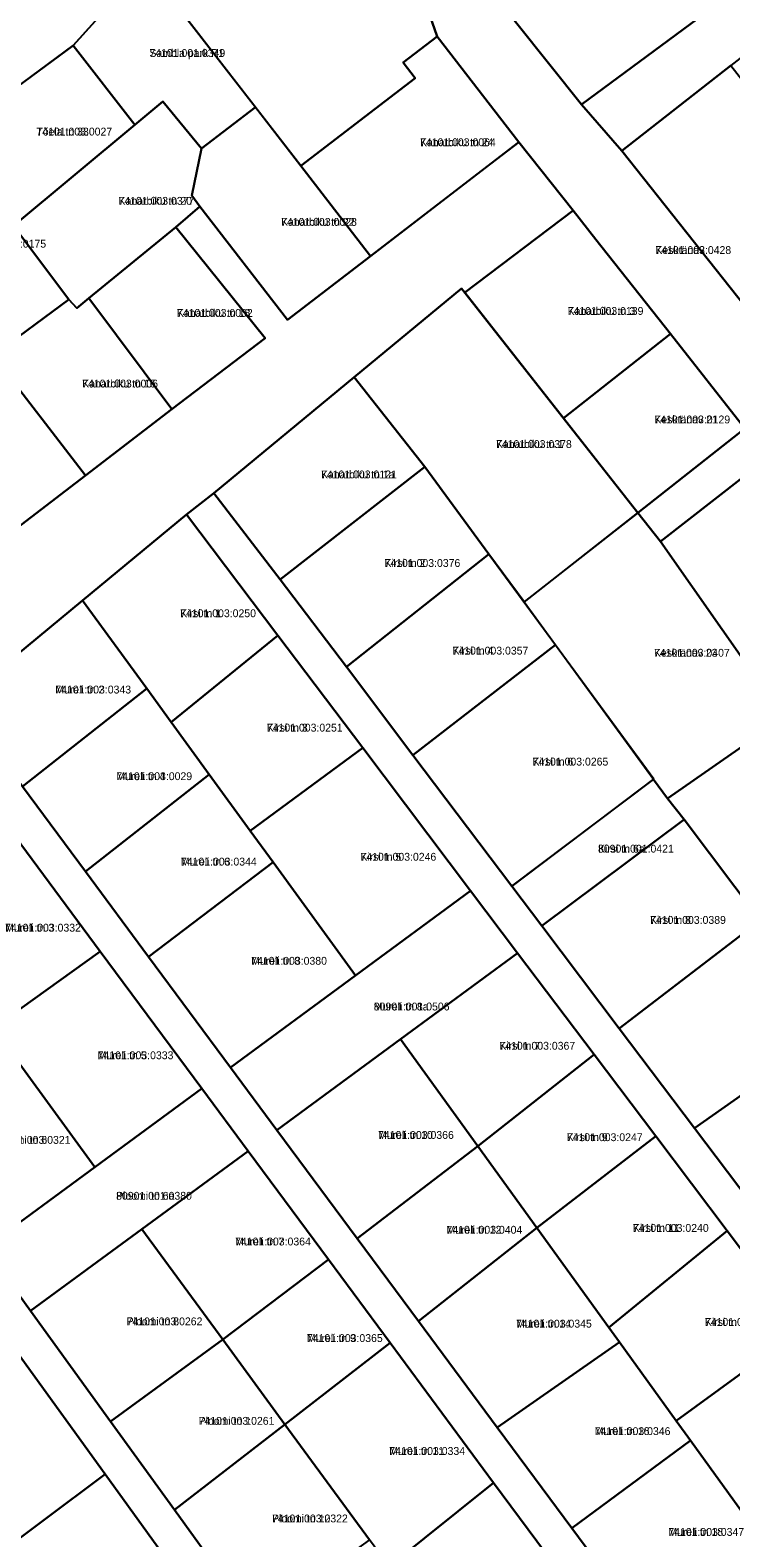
# Model space of a CAD drawing. Extents: x 524000 to 564260, y 6469338 to 6496391.
# Drawn here: x 538832.2 to 538966.3, y 6473209.4 to 6473497.9 of the extents above; entities that cross this region are included whole.
import ezdxf

# ---------------------------------------------------------------- set-up
doc = ezdxf.new("R2010")
doc.units = 0
for name, color, linetype in [('L_AADRESS', 7, 'Continuous'), ('PIIR', 7, 'Continuous'), ('TUNNUS', 7, 'Continuous')]:
    doc.layers.add(name, color=color, linetype=linetype)

msp = doc.modelspace()

# ---------------------------------------------------------------- linework, layer by layer
at = {"layer": 'PIIR'}
for points in [[(538790.44, 6473668.85), (538818.36, 6473633.78), (538821.51, 6473636.25), (538833.78, 6473620.41), (538846.45, 6473604.93), (538843.3, 6473602.49), (538860.15, 6473582.87), (538863.79, 6473577.89), (538881.97, 6473554.41), (538900.33, 6473530.7), (538918.99, 6473507.21), (538937.65, 6473483.72), (538945.42, 6473474.85), (538974.45, 6473438.22), (538987.99, 6473421.14), (539019.92, 6473380.27), (539033.35, 6473363.32), (539046.78, 6473346.15), (539060.21, 6473328.98), (539073.64, 6473311.81), (539082.11, 6473303.28), (539135.86, 6473234.01), (539149.77, 6473216.07), (539153.84, 6473218.89)], [(538973.59, 6473416.31), (538952.77, 6473400.07), (538948.47, 6473405.56), (538968.92, 6473421.73), (538954.69, 6473439.8), (538940.44, 6473457.89), (538936.11, 6473463.39), (538925.69, 6473476.49), (538910.07, 6473496.74), (538906.42, 6473507.17)], [(538795.36, 6473376.39), (538842.75, 6473412.69), (538859.26, 6473425.42), (538877.16, 6473439), (538860.04, 6473460.24), (538864.62, 6473464.21), (538881.44, 6473442.51), (538897.28, 6473454.71), (538925.69, 6473476.49), (538936.11, 6473463.39), (538915.37, 6473447.7), (538914.74, 6473448.5), (538894.18, 6473431.5), (538867.33, 6473409.3), (538862.09, 6473405.24), (538842.2, 6473388.81), (538818.72, 6473369.4)], [(538979.8, 6473249.3), (538965.56, 6473268.15), (538951.88, 6473286.28), (538940.1, 6473301.9), (538925.46, 6473321.29), (538916.46, 6473333.21), (538895.81, 6473360.57), (538879.58, 6473382.07), (538862.09, 6473405.24), (538867.33, 6473409.3), (538880.04, 6473392.82), (538892.7, 6473376.06), (538905.42, 6473359.21), (538924.36, 6473334.11), (538930.08, 6473326.52), (538944.9, 6473306.89), (538959.3, 6473287.82), (538971.92, 6473271.1)], [(538939.08, 6473195.34), (538920.87, 6473219.93), (538901.05, 6473246.69), (538889.24, 6473262.65), (538873.87, 6473283.41), (538865, 6473295.39), (538845.6, 6473321.61), (538829.29, 6473343.63), (538813.44, 6473365.04), (538818.72, 6473369.4), (538830.74, 6473353.18), (538842.79, 6473336.9), (538854.85, 6473320.6), (538870.51, 6473299.44), (538879.39, 6473287.45), (538894.78, 6473266.66), (538906.47, 6473250.87), (538921.54, 6473230.53), (538935.8, 6473211.27), (538950.43, 6473191.51)], [(538867.2, 6473192.97), (538846.51, 6473221.58), (538814.6, 6473265.73), (538803.57, 6473280.99), (538793.08, 6473295.5), (538782.67, 6473309.9), (538769.22, 6473328.51), (538774.43, 6473332.82), (538792.14, 6473308.32), (538806.26, 6473288.78), (538823.52, 6473264.91), (538832.26, 6473252.82), (538847.53, 6473231.69), (538859.8, 6473214.73), (538875.33, 6473193.24)]]:
    msp.add_lwpolyline(points, dxfattribs=at)
for points in [[(539082.21, 6473592.27), (539089.25, 6473583.53), (539062.91, 6473564.58), (539042.54, 6473549.92), (539021.31, 6473533.32), (538997.68, 6473514.83), (538986.76, 6473507.2), (538966.28, 6473491.18), (538945.42, 6473474.85), (538937.65, 6473483.72), (538977.91, 6473513.5), (538989.08, 6473522.31), (539013.41, 6473539.87), (539012.78, 6473540.65), (539033.15, 6473556.97), (539056.61, 6473573.98), (539079.77, 6473590.52)], [(538874.33, 6473545.46), (538883.08, 6473536.52), (538854.24, 6473510.36), (538840.44, 6473495.03), (538816.26, 6473477.19), (538801.85, 6473465.94), (538760.64, 6473420.14), (538745.93, 6473401.69), (538729.29, 6473380.83), (538718, 6473394.65), (538732.82, 6473416.15), (538732.08, 6473417.02), (538750.86, 6473441.68), (538751.83, 6473440.29), (538772.8, 6473468.56), (538782.98, 6473484.33), (538801.98, 6473508.7), (538815.58, 6473527.22), (538831.5, 6473506.61)], [(538918.99, 6473507.21), (538959.23, 6473536.98), (538977.91, 6473513.5), (538937.65, 6473483.72)], [(538906.42, 6473507.17), (538910.07, 6473496.74), (538903.58, 6473491.73), (538905.87, 6473488.76), (538883.99, 6473471.98), (538878.96, 6473478.47), (538854.24, 6473510.36), (538883.08, 6473536.52)], [(538852.18, 6473479.83), (538840.44, 6473495.03), (538854.24, 6473510.36), (538875.28, 6473483.21), (538864.96, 6473475.26), (538857.56, 6473484.31)], [(538883.99, 6473471.98), (538905.87, 6473488.76), (538903.58, 6473491.73), (538910.07, 6473496.74), (538925.69, 6473476.49), (538919.18, 6473471.5), (538897.28, 6473454.71)], [(538828.96, 6473460.5), (538816.26, 6473477.19), (538816.29, 6473477.21), (538840.44, 6473495.03), (538852.18, 6473479.83)], [(538980.5, 6473473), (538989.49, 6473460.78), (538994.43, 6473454.06), (538974.45, 6473438.22), (538945.42, 6473474.85), (538966.28, 6473491.18)], [(538860.04, 6473460.24), (538843.38, 6473446.66), (538841.08, 6473444.74), (538839.6, 6473446.42), (538828.96, 6473460.5), (538852.18, 6473479.83), (538857.56, 6473484.31), (538864.96, 6473475.26), (538863.11, 6473466.26), (538864.62, 6473464.21)], [(538881.44, 6473442.51), (538864.62, 6473464.21), (538863.11, 6473466.26), (538864.96, 6473475.26), (538875.28, 6473483.21), (538883.99, 6473471.98), (538897.28, 6473454.71)], [(538816.26, 6473477.19), (538828.96, 6473460.5), (538839.6, 6473446.42), (538825.02, 6473435.7), (538801.85, 6473465.94)], [(538801.85, 6473465.94), (538825.02, 6473435.7), (538842.75, 6473412.69), (538795.36, 6473376.39), (538780.2, 6473395.5), (538760.64, 6473420.14)], [(538915.37, 6473447.7), (538936.11, 6473463.39), (538940.44, 6473457.89), (538954.69, 6473439.8), (538934.26, 6473423.71), (538920.01, 6473441.8)], [(538860.04, 6473460.24), (538877.16, 6473439), (538859.26, 6473425.42), (538843.38, 6473446.66)], [(538907.72, 6473414.36), (538894.18, 6473431.5), (538914.74, 6473448.5), (538948.47, 6473405.56), (538926.7, 6473388.5), (538919.97, 6473397.66)], [(538839.6, 6473446.42), (538841.08, 6473444.74), (538843.38, 6473446.66), (538859.26, 6473425.42), (538842.75, 6473412.69), (538825.02, 6473435.7)], [(538934.26, 6473423.71), (538954.69, 6473439.8), (538968.92, 6473421.73), (538948.47, 6473405.56)], [(538907.72, 6473414.36), (538880.04, 6473392.82), (538867.33, 6473409.3), (538894.18, 6473431.5)], [(538973.59, 6473416.31), (538999.46, 6473383.2), (538976.38, 6473366.41), (538952.77, 6473400.07)], [(538880.04, 6473392.82), (538907.72, 6473414.36), (538919.97, 6473397.66), (538892.7, 6473376.06)], [(538879.58, 6473382.07), (538859.15, 6473365.53), (538854.5, 6473371.92), (538842.2, 6473388.81), (538862.09, 6473405.24)], [(538948.47, 6473405.56), (538952.77, 6473400.07), (538976.38, 6473366.41), (538954.12, 6473350.91), (538951.46, 6473354.55), (538932.72, 6473380.21), (538926.71, 6473388.44)], [(538932.73, 6473380.29), (538905.42, 6473359.21), (538892.7, 6473376.06), (538919.97, 6473397.66)], [(538854.5, 6473371.92), (538830.74, 6473353.18), (538818.72, 6473369.4), (538842.2, 6473388.81)], [(538895.81, 6473360.57), (538874.31, 6473344.7), (538866.44, 6473355.51), (538859.15, 6473365.53), (538879.58, 6473382.07)], [(538951.53, 6473354.67), (538924.36, 6473334.11), (538905.42, 6473359.21), (538932.73, 6473380.29)], [(538830.74, 6473353.18), (538854.5, 6473371.92), (538859.15, 6473365.53), (538866.44, 6473355.51), (538842.79, 6473336.9)], [(538976.38, 6473366.41), (539000.5, 6473336.39), (539002.72, 6473333.71), (538983.57, 6473319), (538980.21, 6473316.42), (538971.86, 6473327.53), (538957.3, 6473346.9), (538954.12, 6473350.91)], [(538874.31, 6473344.7), (538895.81, 6473360.57), (538916.46, 6473333.21), (538894.45, 6473317.04), (538878.67, 6473338.71)], [(538874.31, 6473344.7), (538878.67, 6473338.71), (538854.85, 6473320.6), (538842.79, 6473336.9), (538866.44, 6473355.51)], [(538957.3, 6473346.9), (538930.08, 6473326.52), (538924.36, 6473334.11), (538951.46, 6473354.55), (538954.12, 6473350.91)], [(538957.3, 6473346.9), (538971.86, 6473327.53), (538944.9, 6473306.89), (538930.08, 6473326.52)], [(538845.6, 6473321.61), (538825.18, 6473307.02), (538813.64, 6473322.92), (538809.17, 6473329.07), (538829.29, 6473343.63)], [(538854.85, 6473320.6), (538878.67, 6473338.71), (538894.45, 6473317.04), (538870.51, 6473299.44)], [(538903.07, 6473304.84), (538879.39, 6473287.45), (538870.51, 6473299.44), (538894.45, 6473317.04), (538916.46, 6473333.21), (538925.46, 6473321.29)], [(538944.9, 6473306.89), (538971.86, 6473327.53), (538980.21, 6473316.42), (538987.02, 6473307.32), (538959.3, 6473287.82)], [(538825.18, 6473307.02), (538845.6, 6473321.61), (538865, 6473295.39), (538844.54, 6473280.35), (538826.98, 6473304.53)], [(538903.07, 6473304.84), (538925.46, 6473321.29), (538940.1, 6473301.9), (538917.87, 6473284.34)], [(538959.3, 6473287.82), (538987.02, 6473307.32), (539000.34, 6473289.53), (538971.92, 6473271.1)], [(538806.26, 6473288.78), (538826.98, 6473304.53), (538844.54, 6473280.35), (538823.52, 6473264.91)], [(538879.39, 6473287.45), (538903.07, 6473304.84), (538917.87, 6473284.34), (538894.78, 6473266.66)], [(538951.88, 6473286.28), (538929.13, 6473268.75), (538917.87, 6473284.34), (538940.1, 6473301.9)], [(538853.54, 6473268.46), (538832.26, 6473252.82), (538823.52, 6473264.91), (538844.54, 6473280.35), (538865, 6473295.39), (538873.87, 6473283.41)], [(538929.13, 6473268.75), (538951.88, 6473286.28), (538965.56, 6473268.15), (538942.92, 6473249.65)], [(538853.54, 6473268.46), (538873.87, 6473283.41), (538889.24, 6473262.65), (538869.03, 6473247.35)], [(538917.87, 6473284.34), (538929.13, 6473268.75), (538906.47, 6473250.87), (538894.78, 6473266.66)], [(538832.26, 6473252.82), (538853.54, 6473268.46), (538869.03, 6473247.35), (538847.53, 6473231.69)], [(538906.47, 6473250.87), (538929.13, 6473268.75), (538942.92, 6473249.65), (538944.93, 6473246.86), (538921.54, 6473230.53)], [(538822.63, 6473203.75), (538794.97, 6473183.11), (538762.53, 6473227.53), (538791.04, 6473248.2), (538814.6, 6473265.73), (538846.51, 6473221.58)], [(538979.8, 6473249.3), (538955.82, 6473231.78), (538944.93, 6473246.86), (538942.92, 6473249.65), (538965.56, 6473268.15)], [(538869.03, 6473247.35), (538889.24, 6473262.65), (538901.05, 6473246.69), (538880.94, 6473231.12)], [(538958.51, 6473228.05), (538955.82, 6473231.78), (538979.8, 6473249.3), (538992.9, 6473231.95), (538969.45, 6473212.9)], [(538880.94, 6473231.12), (538859.8, 6473214.73), (538847.53, 6473231.69), (538869.03, 6473247.35)], [(538920.87, 6473219.93), (538900.88, 6473203.94), (538897.13, 6473209.04), (538880.94, 6473231.12), (538901.05, 6473246.69)], [(538921.54, 6473230.53), (538944.93, 6473246.86), (538955.82, 6473231.78), (538958.51, 6473228.05), (538935.8, 6473211.27)], [(538897.13, 6473209.04), (538875.33, 6473193.24), (538859.8, 6473214.73), (538880.94, 6473231.12)], [(538935.8, 6473211.27), (538958.51, 6473228.05), (538969.45, 6473212.9), (538972.93, 6473208.08), (538950.43, 6473191.51)], [(538822.63, 6473203.75), (538846.51, 6473221.58), (538867.2, 6473192.97), (538843.18, 6473175.12), (538842.08, 6473176.65)], [(538900.88, 6473203.94), (538920.87, 6473219.93), (538939.08, 6473195.34), (538918.73, 6473179.61), (538910.96, 6473190.19)]]:
    msp.add_lwpolyline(points, close=True, dxfattribs=at)

# ---------------------------------------------------------------- texts
at = {"layer": 'L_AADRESS'}
for s, p in [('Sambla park P1', (538855, 6473492.81)), ('Tõela tn 33', (538833.37, 6473477.77)), ('Kanarbiku tn 24', (538906.78, 6473475.73)), ('Kanarbiku tn 20', (538849.09, 6473464.52)), ('Kanarbiku tn 22', (538880.2, 6473460.49)), ('Kesktänav', (538951.82, 6473455.1)), ('Kanarbiku tn 18', (538860.27, 6473443.07)), ('Kanarbiku tn 3', (538935.03, 6473443.44)), ('Kanarbiku tn 16', (538842.14, 6473429.55)), ('Kesktänav 21', (538951.62, 6473422.68)), ('Kanarbiku tn 1', (538921.32, 6473417.97)), ('Kanarbiku tn 1a', (538887.84, 6473412.16)), ('Kirsi tn 2', (538899.99, 6473395.21)), ('Kirsi tn 1', (538860.89, 6473385.59)), ('Kirsi tn 4', (538913.01, 6473378.44)), ('Kesktänav 23', (538951.55, 6473378.03)), ('Mureli tn 2', (538836.99, 6473370.99)), ('Kirsi tn 3', (538877.48, 6473363.7)), ('Kirsi tn 6', (538928.31, 6473357.2)), ('Mureli tn 4', (538848.67, 6473354.41)), ('Kirsi tn 5', (538895.39, 6473338.99)), ('Kirsi tn 6a', (538940.84, 6473340.54)), ('Mureli tn 6', (538861.03, 6473338.06)), ('Mureli tn 3', (538827.39, 6473325.42)), ('Kirsi tn 8', (538950.81, 6473326.9)), ('Mureli tn 8', (538874.47, 6473319.08)), ('Mureli tn 8a', (538897.93, 6473310.33)), ('Kirsi tn 7', (538921.97, 6473302.82)), ('Mureli tn 5', (538845.09, 6473301)), ('Ploomi tn 6', (538825.4, 6473284.81)), ('Mureli tn 10', (538898.75, 6473285.75)), ('Kirsi tn 9', (538934.88, 6473285.32)), ('Ploomi tn 6a', (538848.63, 6473274.11)), ('Mureli tn 12', (538911.85, 6473267.61)), ('Kirsi tn 11', (538947.52, 6473267.96)), ('Mureli tn 7', (538871.39, 6473265.36)), ('Ploomi tn 8', (538850.64, 6473250.08)), ('Mureli tn 14', (538925.15, 6473249.64)), ('Kirsi tn 13', (538961.3, 6473249.96)), ('Mureli tn 9', (538885.14, 6473246.88)), ('Ploomi tn 10', (538864.42, 6473231.04)), ('Mureli tn 16', (538940.2, 6473229.07)), ('Mureli tn 11', (538900.9, 6473225.27)), ('Ploomi tn 12', (538878.46, 6473212.36)), ('Mureli tn 18', (538954.3, 6473209.78))]:
    msp.add_text(s, height=1.5, dxfattribs=at).set_placement(p)
at = {"layer": 'TUNNUS'}
for s, p in [('74101:001:0349', (538855, 6473492.81)), ('74101:003:0027', (538833.37, 6473477.77)), ('74101:003:0064', (538906.78, 6473475.73)), ('74101:003:0377', (538849.09, 6473464.52)), ('74101:003:0028', (538880.2, 6473460.49)), ('74101:003:0175', (538820.73, 6473456.31)), ('74101:003:0428', (538951.82, 6473455.1)), ('74101:003:0002', (538860.27, 6473443.07)), ('74101:003:0139', (538935.03, 6473443.44)), ('74101:003:0006', (538842.14, 6473429.55)), ('74101:003:0129', (538951.62, 6473422.68)), ('74101:003:0378', (538921.32, 6473417.97)), ('74101:003:0121', (538887.84, 6473412.16)), ('74101:003:0376', (538899.99, 6473395.21)), ('74101:003:0250', (538860.89, 6473385.59)), ('74101:003:0357', (538913.01, 6473378.44)), ('74101:003:0407', (538951.55, 6473378.03)), ('74101:003:0343', (538836.99, 6473370.99)), ('74101:003:0251', (538877.48, 6473363.7)), ('74101:003:0265', (538928.31, 6473357.2)), ('74101:003:0029', (538848.67, 6473354.41)), ('74101:003:0246', (538895.39, 6473338.99)), ('80901:001:0421', (538940.84, 6473340.54)), ('74101:003:0344', (538861.03, 6473338.06)), ('74101:003:0332', (538827.39, 6473325.42)), ('74101:003:0389', (538950.81, 6473326.9)), ('74101:003:0380', (538874.47, 6473319.08)), ('80901:001:0506', (538897.93, 6473310.33)), ('74101:003:0367', (538921.97, 6473302.82)), ('74101:003:0333', (538845.09, 6473301)), ('74101:003:0321', (538825.4, 6473284.81)), ('74101:003:0366', (538898.75, 6473285.75)), ('74101:003:0247', (538934.88, 6473285.32)), ('80901:001:0380', (538848.63, 6473274.11)), ('74101:003:0404', (538911.85, 6473267.61)), ('74101:003:0240', (538947.52, 6473267.96)), ('74101:003:0364', (538871.39, 6473265.36)), ('74101:003:0262', (538850.64, 6473250.08)), ('74101:003:0345', (538925.15, 6473249.64)), ('74101:003:0353', (538961.3, 6473249.96)), ('74101:003:0365', (538885.14, 6473246.88)), ('74101:003:0261', (538864.42, 6473231.04)), ('74101:003:0346', (538940.2, 6473229.07)), ('74101:003:0334', (538900.9, 6473225.27)), ('74101:003:0322', (538878.46, 6473212.36)), ('74101:003:0347', (538954.3, 6473209.78))]:
    msp.add_text(s, height=1.5, dxfattribs=at).set_placement(p)

doc.saveas('drawing.dxf')
